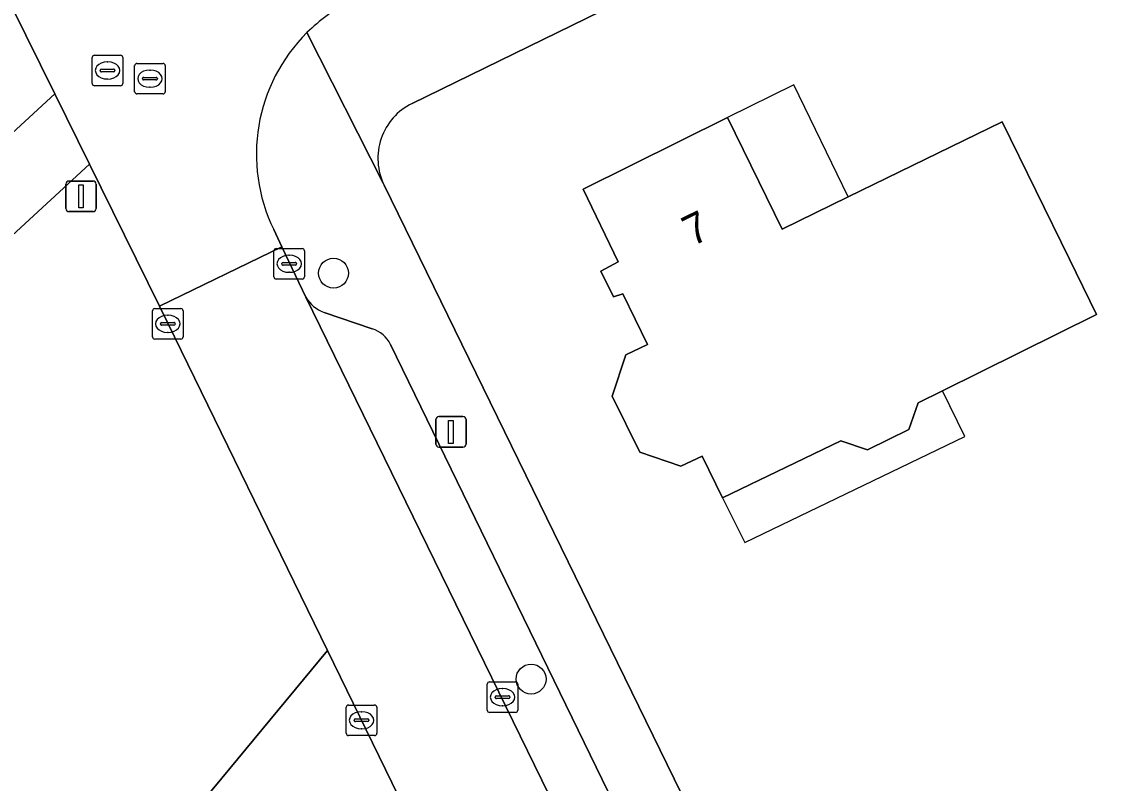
# Model space of a CAD drawing. Extents: x 160455 to 162082, y 388339 to 389736.
# Drawn here: x 160764.68 to 160800.3, y 388623.81 to 388648.73 of the extents above; entities that cross this region are included whole.
import ezdxf

# ---------------------------------------------------------------- set-up
doc = ezdxf.new("R2010")
doc.units = 0
for name, color, linetype in [('IMGEO_Boom', 7, 'Continuous'), ('IMGEO_Erf', 7, 'Continuous'), ('IMGEO_Groenvoorziening', 7, 'Continuous'), ('IMGEO_Kolk', 7, 'Continuous'), ('IMGEO_Lichtmast', 7, 'Continuous'), ('IMGEO_Pand', 7, 'Continuous'), ('IMGEO_Pand_nummerreeks', 7, 'Continuous'), ('IMGEO_Pand_overbouw', 7, 'Continuous'), ('IMGEO_Parkeervlak_open', 7, 'Continuous'), ('IMGEO_Rijbaan_lokaal_open', 7, 'Continuous'), ('IMGEO_Rioolput', 7, 'Continuous'), ('IMGEO_Voetpad_open', 7, 'Continuous')]:
    doc.layers.add(name, color=color, linetype=linetype)

msp = doc.modelspace()

# ---------------------------------------------------------------- linework, layer by layer
at = {"layer": 'IMGEO_Boom'}
for centre in [(160774.883, 388640.505), (160781.349, 388627.22)]:
    msp.add_circle(centre, 0.489, dxfattribs=at)
at = {"layer": 'IMGEO_Erf'}
for points in [[(160828.347, 388670.932), (160777.455, 388646.059)], [(160776.541, 388643.382), (160788.81, 388618.259)]]:
    msp.add_lwpolyline(points, dxfattribs=at)
msp.add_lwpolyline([(160787.615, 388633.148), (160786.95, 388634.517), (160786.249, 388634.188), (160784.909, 388634.649), (160784.005, 388636.474), (160784.453, 388637.827), (160785.156, 388638.175), (160784.348, 388639.831), (160784.042, 388639.726), (160783.63, 388640.568), (160784.199, 388640.874), (160783.058, 388643.254), (160787.772, 388645.597), (160789.57, 388641.947), (160791.725, 388642.998), (160796.771, 388645.458), (160798.965, 388640.966), (160799.852, 388639.15), (160794.809, 388636.654), (160794.022, 388636.26), (160793.707, 388635.386), (160792.363, 388634.724), (160791.488, 388635.019)], close=True, dxfattribs=at)
msp.add_arc((160778.327, 388644.267), 1.993, 115.9534, 206.344, dxfattribs=at)
at = {"layer": 'IMGEO_Groenvoorziening'}
for points in [[(160745.684, 388627.869), (160765.757, 388646.373), (160764.339, 388649.243), (160728.628, 388660.472)], [(160732.41, 388589.872), (160730.352, 388585.682), (160737.183, 388582.808), (160737.308, 388582.959), (160767.455, 388619.42), (160774.68, 388628.159), (160769.46, 388638.873), (160769.189, 388639.422), (160766.892, 388644.075), (160741.437, 388620.594)], [(160782.482, 388612.146), (160774.68, 388628.159), (160767.455, 388619.42), (160780.727, 388601.005), (160762.874, 388583.451), (160753.488, 388577.188), (160737.308, 388582.959), (160737.183, 388582.808), (160749.273, 388577.722), (160754.912, 388575.034), (160758.62, 388573.265), (160761.837, 388571.625), (160764.372, 388569.92), (160780.049, 388559.896), (160785.479, 388556.642)]]:
    msp.add_lwpolyline(points, dxfattribs=at)
at = {"layer": 'IMGEO_Kolk'}
for p, q in [((160772.932, 388640.386), (160772.932, 388641.238)), ((160773.007, 388641.312), (160773.859, 388641.312)), ((160773.42, 388641.092), (160773.445, 388641.092)), ((160773.933, 388641.238), (160773.933, 388640.386)), ((160773.191, 388640.806), (160773.191, 388640.818)), ((160773.629, 388640.769), (160773.231, 388640.769)), ((160773.234, 388640.855), (160773.632, 388640.855)), ((160773.675, 388640.818), (160773.675, 388640.806)), ((160773.443, 388640.532), (160773.418, 388640.532)), ((160773.859, 388640.312), (160773.007, 388640.312)), ((160768.958, 388638.419), (160768.958, 388639.271)), ((160769.033, 388639.345), (160769.885, 388639.345)), ((160769.959, 388639.271), (160769.959, 388638.419)), ((160769.446, 388639.125), (160769.471, 388639.125)), ((160769.217, 388638.839), (160769.217, 388638.851)), ((160769.655, 388638.802), (160769.257, 388638.802)), ((160769.26, 388638.888), (160769.658, 388638.888)), ((160769.469, 388638.565), (160769.444, 388638.565)), ((160769.701, 388638.851), (160769.701, 388638.839)), ((160769.885, 388638.345), (160769.033, 388638.345)), ((160779.914, 388626.201), (160779.914, 388627.053)), ((160779.989, 388627.127), (160780.841, 388627.127)), ((160780.402, 388626.907), (160780.427, 388626.907)), ((160780.915, 388627.053), (160780.915, 388626.201)), ((160780.173, 388626.621), (160780.173, 388626.633)), ((160780.611, 388626.584), (160780.213, 388626.584)), ((160780.216, 388626.67), (160780.614, 388626.67)), ((160780.657, 388626.633), (160780.657, 388626.621)), ((160775.3, 388625.445), (160775.3, 388626.297)), ((160775.375, 388626.371), (160776.227, 388626.371)), ((160775.788, 388626.151), (160775.813, 388626.151)), ((160776.301, 388626.297), (160776.301, 388625.445)), ((160780.841, 388626.127), (160779.989, 388626.127)), ((160780.425, 388626.347), (160780.4, 388626.347)), ((160775.559, 388625.865), (160775.559, 388625.877)), ((160775.997, 388625.828), (160775.599, 388625.828)), ((160775.602, 388625.914), (160776, 388625.914)), ((160776.043, 388625.877), (160776.043, 388625.865)), ((160776.227, 388625.371), (160775.375, 388625.371)), ((160775.811, 388625.591), (160775.786, 388625.591))]:
    msp.add_line(p, q, dxfattribs=at)
for points in [[(160772.932, 388640.386), (160772.932, 388641.238)], [(160773.007, 388641.312), (160773.859, 388641.312)], [(160773.933, 388641.238), (160773.933, 388640.386)], [(160773.859, 388640.312), (160773.007, 388640.312)], [(160768.958, 388638.419), (160768.958, 388639.271)], [(160769.033, 388639.345), (160769.885, 388639.345)], [(160769.959, 388639.271), (160769.959, 388638.419)], [(160769.885, 388638.345), (160769.033, 388638.345)], [(160779.914, 388626.201), (160779.914, 388627.053)], [(160779.989, 388627.127), (160780.841, 388627.127)], [(160780.915, 388627.053), (160780.915, 388626.201)], [(160775.3, 388625.445), (160775.3, 388626.297)], [(160775.375, 388626.371), (160776.227, 388626.371)], [(160776.301, 388626.297), (160776.301, 388625.445)], [(160780.841, 388626.127), (160779.989, 388626.127)], [(160776.227, 388625.371), (160775.375, 388625.371)]]:
    msp.add_lwpolyline(points, dxfattribs=at)
for centre, radius, start, end in [((160773.009, 388641.236), 0.0765, 91.552, 178.448), ((160773.009, 388641.236), 0.0765, 91.552, 178.448), ((160773.857, 388641.236), 0.0765, 1.552, 88.448), ((160773.857, 388641.236), 0.0765, 1.552, 88.448), ((160773.231, 388640.815), 0.0403, 85.8775, 175.7526), ((160773.228, 388640.805), 0.0366, 178.938, 274.7102), ((160773.632, 388640.812), 0.043, 264.8664, 352.4533), ((160773.636, 388640.817), 0.0386, 1.7309, 96.639), ((160773.009, 388640.388), 0.0765, 181.552, 268.448), ((160773.009, 388640.388), 0.0765, 181.552, 268.448), ((160773.857, 388640.388), 0.0765, 271.552, 358.448), ((160773.857, 388640.388), 0.0765, 271.552, 358.448), ((160769.035, 388639.269), 0.0765, 91.552, 178.448), ((160769.035, 388639.269), 0.0765, 91.552, 178.448), ((160769.883, 388639.269), 0.0765, 1.552, 88.448), ((160769.883, 388639.269), 0.0765, 1.552, 88.448), ((160769.257, 388638.848), 0.0403, 85.8775, 175.7526), ((160769.254, 388638.838), 0.0366, 178.938, 274.7102), ((160769.658, 388638.845), 0.043, 264.8664, 352.4533), ((160769.662, 388638.85), 0.0386, 1.7309, 96.639), ((160769.035, 388638.421), 0.0765, 181.552, 268.448), ((160769.035, 388638.421), 0.0765, 181.552, 268.448), ((160769.883, 388638.421), 0.0765, 271.552, 358.448), ((160769.883, 388638.421), 0.0765, 271.552, 358.448), ((160779.991, 388627.051), 0.0765, 91.552, 178.448), ((160779.991, 388627.051), 0.0765, 91.552, 178.448), ((160780.839, 388627.051), 0.0765, 1.552, 88.448), ((160780.839, 388627.051), 0.0765, 1.552, 88.448), ((160780.213, 388626.63), 0.0403, 85.8775, 175.7526), ((160780.21, 388626.62), 0.0366, 178.938, 274.7102), ((160780.614, 388626.627), 0.043, 264.8664, 352.4533), ((160780.618, 388626.632), 0.0386, 1.7309, 96.639), ((160775.377, 388626.295), 0.0765, 91.552, 178.448), ((160775.377, 388626.295), 0.0765, 91.552, 178.448), ((160776.225, 388626.295), 0.0765, 1.552, 88.448), ((160776.225, 388626.295), 0.0765, 1.552, 88.448), ((160779.991, 388626.203), 0.0765, 181.552, 268.448), ((160779.991, 388626.203), 0.0765, 181.552, 268.448), ((160780.839, 388626.203), 0.0765, 271.552, 358.448), ((160780.839, 388626.203), 0.0765, 271.552, 358.448), ((160775.599, 388625.874), 0.0403, 85.8775, 175.7526), ((160775.596, 388625.864), 0.0366, 178.938, 274.7102), ((160776, 388625.871), 0.043, 264.8664, 352.4533), ((160776.004, 388625.876), 0.0386, 1.7309, 96.639), ((160775.377, 388625.447), 0.0765, 181.552, 268.448), ((160775.377, 388625.447), 0.0765, 181.552, 268.448), ((160776.225, 388625.447), 0.0765, 271.552, 358.448), ((160776.225, 388625.447), 0.0765, 271.552, 358.448)]:
    msp.add_arc(centre, radius, start, end, dxfattribs=at)
for centre, major_axis, ratio, start_param, end_param in [((160773.419, 388640.812), (-0.387, 0.002), 0.722429, 4.712389, 7.853982), ((160773.444, 388640.812), (-0.39, 0.002), 0.717154, 1.570796, 4.712389), ((160769.445, 388638.845), (-0.387, 0.002), 0.722429, 4.712389, 7.853982), ((160769.47, 388638.845), (-0.39, 0.002), 0.717154, 1.570796, 4.712389), ((160780.401, 388626.627), (-0.387, 0.002), 0.722429, 4.712389, 7.853982), ((160780.426, 388626.627), (-0.39, 0.002), 0.717154, 1.570796, 4.712389), ((160775.787, 388625.871), (-0.387, 0.002), 0.722429, 4.712389, 7.853982), ((160775.812, 388625.871), (-0.39, 0.002), 0.717154, 1.570796, 4.712389)]:
    msp.add_ellipse(centre, major_axis=major_axis, ratio=ratio, start_param=start_param, end_param=end_param, dxfattribs=at)
at = {"layer": 'IMGEO_Lichtmast'}
for p, q in [((160766.123, 388642.619), (160766.123, 388643.419)), ((160766.123, 388643.419), (160766.123, 388642.619)), ((160766.223, 388643.519), (160767.013, 388643.519)), ((160767.013, 388643.519), (160766.223, 388643.519)), ((160767.113, 388643.419), (160767.113, 388642.619)), ((160767.113, 388642.619), (160767.113, 388643.419)), ((160767.013, 388642.519), (160766.223, 388642.519)), ((160766.223, 388642.519), (160767.013, 388642.519)), ((160778.23, 388634.91), (160778.23, 388635.71)), ((160778.23, 388635.71), (160778.23, 388634.91)), ((160778.33, 388635.81), (160779.12, 388635.81)), ((160779.12, 388635.81), (160778.33, 388635.81)), ((160779.22, 388635.71), (160779.22, 388634.91)), ((160779.22, 388634.91), (160779.22, 388635.71)), ((160779.12, 388634.81), (160778.33, 388634.81)), ((160778.33, 388634.81), (160779.12, 388634.81))]:
    msp.add_line(p, q, dxfattribs=at)
for points in [[(160766.543, 388643.394), (160766.693, 388643.394), (160766.693, 388642.644), (160766.543, 388642.644), (160766.543, 388643.394)], [(160778.65, 388635.685), (160778.8, 388635.685), (160778.8, 388634.935), (160778.65, 388634.935), (160778.65, 388635.685)]]:
    msp.add_lwpolyline(points, dxfattribs=at)
for centre, start, end in [((160766.223, 388643.419), 90, 180), ((160766.223, 388643.419), 90, 180), ((160767.013, 388643.419), 0, 90), ((160767.013, 388643.419), 360, 90), ((160766.223, 388642.619), 180, 270), ((160766.223, 388642.619), 180, 270), ((160767.013, 388642.619), 270, 0), ((160767.013, 388642.619), 270, 0), ((160778.33, 388635.71), 90, 180), ((160778.33, 388635.71), 90, 180), ((160779.12, 388635.71), 0, 90), ((160779.12, 388635.71), 360, 90), ((160778.33, 388634.91), 180, 270), ((160778.33, 388634.91), 180, 270), ((160779.12, 388634.91), 270, 0), ((160779.12, 388634.91), 270, 0)]:
    msp.add_arc(centre, 0.1, start, end, dxfattribs=at)
at = {"layer": 'IMGEO_Pand'}
msp.add_lwpolyline([(160787.772, 388645.597), (160783.058, 388643.254), (160784.199, 388640.874), (160783.63, 388640.568), (160784.042, 388639.726), (160784.348, 388639.831), (160785.156, 388638.175), (160784.453, 388637.827), (160784.005, 388636.474), (160784.909, 388634.649), (160786.249, 388634.188), (160786.95, 388634.517), (160787.615, 388633.148), (160791.488, 388635.019), (160792.363, 388634.724), (160793.707, 388635.386), (160794.022, 388636.26), (160794.809, 388636.654), (160799.852, 388639.15), (160798.965, 388640.966), (160796.771, 388645.458), (160791.725, 388642.998), (160789.57, 388641.947)], close=True, dxfattribs=at)
at = {"layer": 'IMGEO_Pand_overbouw'}
for points in [[(160787.772, 388645.597), (160789.57, 388641.947), (160791.725, 388642.998), (160789.952, 388646.666)], [(160794.809, 388636.654), (160794.022, 388636.26), (160793.707, 388635.386), (160792.363, 388634.724), (160791.488, 388635.019), (160787.615, 388633.148), (160788.343, 388631.688), (160795.545, 388635.162)]]:
    msp.add_lwpolyline(points, close=True, dxfattribs=at)
at = {"layer": 'IMGEO_Parkeervlak_open'}
for points in [[(160773.981, 388639.715), (160786.14, 388614.827), (160786.963, 388613.109), (160788.581, 388613.855), (160788.436, 388614.156), (160776.749, 388638.166)], [(160776.152, 388638.68), (160774.572, 388639.218)]]:
    msp.add_lwpolyline(points, dxfattribs=at)
for centre, radius, start, end in [((160774.958, 388640.277), 1.127, 209.9096, 249.9663), ((160775.865, 388637.743), 0.98, 25.5718, 72.9732)]:
    msp.add_arc(centre, radius, start, end, dxfattribs=at)
at = {"layer": 'IMGEO_Rijbaan_lokaal_open'}
for points in [[(160766.018, 388656.033), (160761.961, 388654.06), (160762.811, 388652.339), (160764.339, 388649.243), (160765.757, 388646.373), (160766.892, 388644.075), (160769.189, 388639.422), (160773.193, 388641.371), (160772.927, 388641.931)], [(160786.963, 388613.109), (160786.14, 388614.827), (160773.981, 388639.715), (160773.193, 388641.371), (160769.189, 388639.422), (160769.46, 388638.873), (160774.68, 388628.159), (160782.482, 388612.146)]]:
    msp.add_lwpolyline(points, dxfattribs=at)
for centre, radius, start, end in [((160777.959, 388644.416), 5.59, 117.1395, 134.886), ((160777.974, 388644.395), 5.616, 134.84, 206.0164)]:
    msp.add_arc(centre, radius, start, end, dxfattribs=at)
at = {"layer": 'IMGEO_Rioolput'}
for p, q in [((160766.986, 388646.713), (160766.986, 388647.565)), ((160767.061, 388647.639), (160767.913, 388647.639)), ((160767.987, 388647.565), (160767.987, 388646.713)), ((160767.245, 388647.133), (160767.245, 388647.145)), ((160767.683, 388647.096), (160767.285, 388647.096)), ((160767.288, 388647.182), (160767.686, 388647.182)), ((160767.474, 388647.419), (160767.499, 388647.419)), ((160767.729, 388647.145), (160767.729, 388647.133)), ((160768.374, 388646.444), (160768.374, 388647.296)), ((160768.449, 388647.37), (160769.301, 388647.37)), ((160768.862, 388647.15), (160768.887, 388647.15)), ((160769.375, 388647.296), (160769.375, 388646.444)), ((160767.497, 388646.859), (160767.472, 388646.859)), ((160768.633, 388646.864), (160768.633, 388646.876)), ((160769.071, 388646.827), (160768.673, 388646.827)), ((160768.676, 388646.913), (160769.074, 388646.913)), ((160769.117, 388646.876), (160769.117, 388646.864)), ((160767.913, 388646.639), (160767.061, 388646.639)), ((160768.885, 388646.59), (160768.86, 388646.59)), ((160769.301, 388646.37), (160768.449, 388646.37))]:
    msp.add_line(p, q, dxfattribs=at)
for points in [[(160766.986, 388646.713), (160766.986, 388647.565)], [(160767.061, 388647.639), (160767.913, 388647.639)], [(160767.987, 388647.565), (160767.987, 388646.713)], [(160768.374, 388646.444), (160768.374, 388647.296)], [(160768.449, 388647.37), (160769.301, 388647.37)], [(160769.375, 388647.296), (160769.375, 388646.444)], [(160767.913, 388646.639), (160767.061, 388646.639)], [(160769.301, 388646.37), (160768.449, 388646.37)]]:
    msp.add_lwpolyline(points, dxfattribs=at)
for centre, radius, start, end in [((160767.063, 388647.563), 0.0765, 91.552, 178.448), ((160767.063, 388647.563), 0.0765, 91.552, 178.448), ((160767.911, 388647.563), 0.0765, 1.552, 88.448), ((160767.911, 388647.563), 0.0765, 1.552, 88.448), ((160767.285, 388647.142), 0.0403, 85.8775, 175.7526), ((160767.282, 388647.132), 0.0366, 178.938, 274.7102), ((160767.686, 388647.139), 0.043, 264.8664, 352.4533), ((160767.69, 388647.144), 0.0386, 1.7309, 96.639), ((160768.451, 388647.294), 0.0765, 91.552, 178.448), ((160768.451, 388647.294), 0.0765, 91.552, 178.448), ((160769.299, 388647.294), 0.0765, 1.552, 88.448), ((160769.299, 388647.294), 0.0765, 1.552, 88.448), ((160768.673, 388646.873), 0.0403, 85.8775, 175.7526), ((160768.67, 388646.863), 0.0366, 178.938, 274.7102), ((160769.074, 388646.87), 0.043, 264.8664, 352.4533), ((160769.078, 388646.875), 0.0386, 1.7309, 96.639), ((160767.063, 388646.715), 0.0765, 181.552, 268.448), ((160767.063, 388646.715), 0.0765, 181.552, 268.448), ((160767.911, 388646.715), 0.0765, 271.552, 358.448), ((160767.911, 388646.715), 0.0765, 271.552, 358.448), ((160768.451, 388646.446), 0.0765, 181.552, 268.448), ((160768.451, 388646.446), 0.0765, 181.552, 268.448), ((160769.299, 388646.446), 0.0765, 271.552, 358.448), ((160769.299, 388646.446), 0.0765, 271.552, 358.448)]:
    msp.add_arc(centre, radius, start, end, dxfattribs=at)
for centre, major_axis, ratio, start_param, end_param in [((160767.473, 388647.139), (-0.387, 0.002), 0.722429, 4.712389, 7.853982), ((160767.498, 388647.139), (-0.39, 0.002), 0.717154, 1.570796, 4.712389), ((160768.861, 388646.87), (-0.387, 0.002), 0.722429, 4.712389, 7.853982), ((160768.886, 388646.87), (-0.39, 0.002), 0.717154, 1.570796, 4.712389)]:
    msp.add_ellipse(centre, major_axis=major_axis, ratio=ratio, start_param=start_param, end_param=end_param, dxfattribs=at)
at = {"layer": 'IMGEO_Voetpad_open'}
for points in [[(160777.455, 388646.059), (160828.347, 388670.932)], [(160788.81, 388618.259), (160776.541, 388643.382), (160776.502, 388643.452), (160774.014, 388648.377)], [(160774.014, 388648.377), (160776.502, 388643.452), (160776.541, 388643.382)], [(160741.365, 388627.899), (160741.437, 388620.594), (160766.892, 388644.075), (160765.757, 388646.373), (160745.684, 388627.869)], [(160772.927, 388641.931), (160773.193, 388641.371), (160773.981, 388639.715)], [(160774.572, 388639.218), (160776.152, 388638.68)], [(160776.749, 388638.166), (160788.436, 388614.156), (160788.886, 388614.372), (160790.463, 388611.094), (160790.013, 388610.878)]]:
    msp.add_lwpolyline(points, dxfattribs=at)
for centre, radius, start, end in [((160777.959, 388644.416), 5.59, 117.1395, 134.886), ((160777.974, 388644.395), 5.616, 134.84, 206.0164), ((160778.327, 388644.267), 1.993, 115.9534, 206.344), ((160774.958, 388640.277), 1.127, 209.9096, 249.9663), ((160775.865, 388637.743), 0.98, 25.5718, 72.9732)]:
    msp.add_arc(centre, radius, start, end, dxfattribs=at)

# ---------------------------------------------------------------- texts
at = {"layer": 'IMGEO_Pand_nummerreeks'}
msp.add_text('7', height=1, rotation=26.4288, dxfattribs=at).set_placement((160786.628, 388641.366))

doc.saveas('drawing.dxf')
